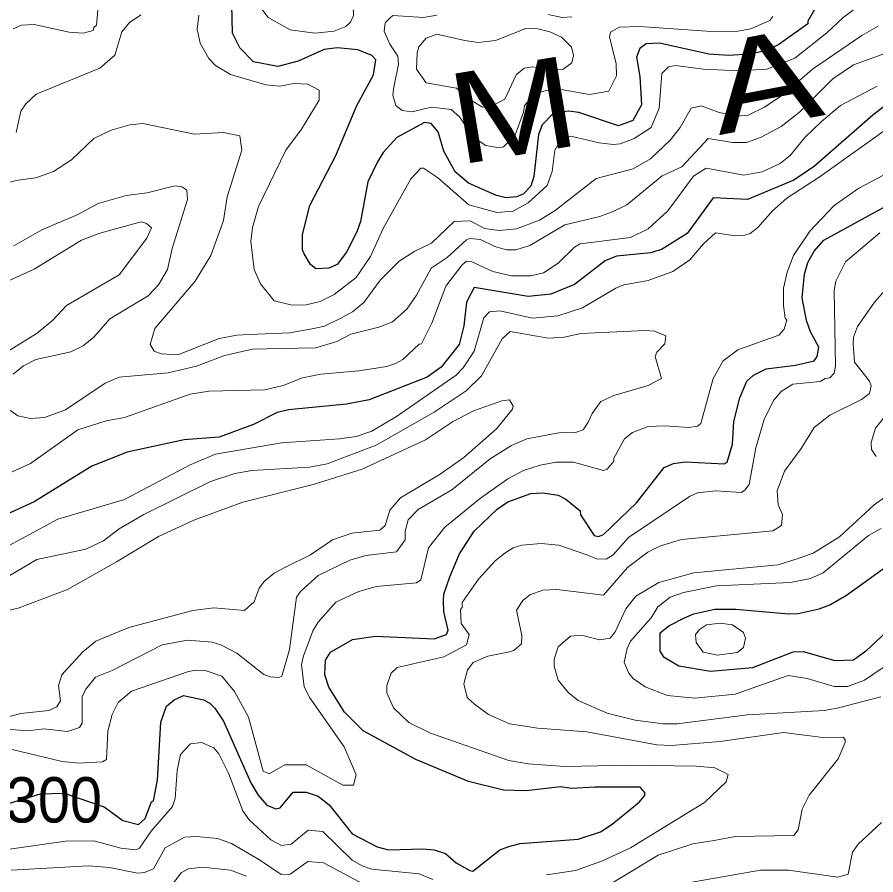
# Model space of a CAD drawing. Extents: x 423 to 448.8, y 7456.3 to 7484.
# Drawn here: x 429.359 to 430.873, y 7468.242 to 7469.755 of the extents above; entities that cross this region are included whole.
import ezdxf
from ezdxf.enums import TextEntityAlignment as Align

# ---------------------------------------------------------------- set-up
doc = ezdxf.new("R2010")
doc.units = 0
doc.header["$LTSCALE"] = 0.032
doc.layers.add('1', color=7, linetype='Continuous', lineweight=25)
doc.layers.add('2', color=7, linetype='Continuous', lineweight=13)
doc.layers.add('61', color=7, linetype='Continuous')

msp = doc.modelspace()

# ---------------------------------------------------------------- linework, layer by layer
at = {"layer": '1'}
for points in [[(430.7694, 7469.7766), (430.7532, 7469.7473), (430.7532, 7469.7426), (430.7022, 7469.7062), (430.679, 7469.6954), (430.6496, 7469.6892), (430.614, 7469.6869), (430.5784, 7469.6892), (430.4918, 7469.7086), (430.4678, 7469.7078), (430.457, 7469.6993), (430.4508, 7469.6838), (430.4569, 7469.6498), (430.46, 7469.6003), (430.4446, 7469.5724), (430.4191, 7469.5632), (430.3495, 7469.5864), (430.3309, 7469.5887), (430.3046, 7469.5856), (430.2845, 7469.5647), (430.2783, 7469.5477), (430.2698, 7469.4735), (430.2644, 7469.4564), (430.2512, 7469.4425), (430.2396, 7469.4379), (430.2211, 7469.4363), (430.2041, 7469.4402), (430.1546, 7469.4618), (430.1313, 7469.4819), (430.1112, 7469.5183), (430.1012, 7469.5523), (430.0888, 7469.567), (430.0772, 7469.5686), (430.0285, 7469.5423), (430.0045, 7469.516), (429.9944, 7469.4998), (429.9774, 7469.4642), (429.9643, 7469.3946), (429.9581, 7469.376), (429.9395, 7469.3404), (429.9233, 7469.3187), (429.9086, 7469.3118), (429.8854, 7469.311), (429.8761, 7469.3188), (429.8653, 7469.3373), (429.8622, 7469.3443), (429.8622, 7469.3714), (429.8753, 7469.4224), (429.921, 7469.5106), (429.9581, 7469.5988), (429.9875, 7469.6529), (429.9913, 7469.6792), (429.9844, 7469.6869), (429.9596, 7469.697), (429.9241, 7469.7008), (429.9001, 7469.6977), (429.8545, 7469.6769), (429.8189, 7469.6676), (429.7755, 7469.6761), (429.7516, 7469.7008), (429.7384, 7469.7263), (429.7376, 7469.7767)], [(430.9064, 7469.6119), (430.8676, 7469.5817), (430.7648, 7469.492), (430.7285, 7469.4673), (430.6465, 7469.4332), (430.5861, 7469.4363), (430.5405, 7469.3729), (430.4964, 7469.3458), (430.4763, 7469.3389), (430.416, 7469.3334), (430.3959, 7469.3249), (430.3417, 7469.2832), (430.3, 7469.2662), (430.2597, 7469.2623), (430.1646, 7469.2777), (430.1515, 7469.2522), (430.1468, 7469.2105), (430.1383, 7469.1772)], [(430.0741, 7468.2885), (430.0942, 7468.2862), (430.1143, 7468.28), (430.1329, 7468.2637), (430.1569, 7468.2498), (430.1622, 7468.249), (430.2102, 7468.2862), (430.2257, 7468.2924), (430.2458, 7468.2978), (430.3479, 7468.3055), (430.3873, 7468.3179), (430.4083, 7468.3318), (430.4554, 7468.3705), (430.4655, 7468.3821), (430.4655, 7468.3875), (430.4577, 7468.3968), (430.3773, 7468.3968), (430.3371, 7468.3944), (430.317, 7468.3975), (430.2567, 7468.3906), (430.2164, 7468.3914), (430.1546, 7468.4068), (430.0617, 7468.4455), (429.9689, 7468.4965), (429.9364, 7468.529), (429.9086, 7468.5731), (429.9016, 7468.5948), (429.9024, 7468.6211), (429.9117, 7468.635), (429.9504, 7468.6574), (429.9906, 7468.6629), (430.0942, 7468.6582), (430.1158, 7468.666), (430.119, 7468.6737), (430.1112, 7468.7062), (430.1105, 7468.7263), (430.1112, 7468.7371), (430.1221, 7468.7681), (430.1391, 7468.8083), (430.1646, 7468.8485), (430.2056, 7468.8872), (430.2242, 7468.9003), (430.2644, 7468.915), (430.286, 7468.9158), (430.3131, 7468.9119), (430.3263, 7468.9049), (430.3518, 7468.884), (430.3525, 7468.8771), (430.3765, 7468.8407), (430.3842, 7468.8392), (430.3928, 7468.8423), (430.4508, 7468.898), (430.4995, 7468.9606), (430.5165, 7468.9676), (430.5366, 7468.9707), (430.6055, 7468.9668), (430.6109, 7468.9699), (430.6202, 7469.0016), (430.6225, 7469.0419), (430.6333, 7469.0836), (430.6457, 7469.113), (430.6573, 7469.1231), (430.6797, 7469.1346), (430.7316, 7469.1409), (430.764, 7469.1486), (430.7694, 7469.1563), (430.7725, 7469.1726), (430.7578, 7469.1997), (430.7509, 7469.2198), (430.7431, 7469.26), (430.747, 7469.3017), (430.7532, 7469.3219), (430.764, 7469.342), (430.781, 7469.3613), (430.9033, 7469.4286)], [(430.1383, 7469.1772), (430.1066, 7469.1377), (430.0819, 7469.12), (429.9798, 7469.0797), (429.9395, 7469.072), (429.8374, 7469.062), (429.8173, 7469.0573), (429.7756, 7469.0364), (429.7152, 7469.014), (429.6534, 7469.0094), (429.5528, 7468.9877), (429.4909, 7468.9629), (429.3888, 7468.9003), (429.327, 7468.8717)], [(430.8924, 7468.6713), (430.8553, 7468.6366), (430.8336, 7468.6211), (430.8012, 7468.6195), (430.7455, 7468.6358), (430.7269, 7468.635), (430.6558, 7468.6072), (430.5815, 7468.601), (430.5258, 7468.6102), (430.4995, 7468.6257), (430.4925, 7468.6365), (430.4925, 7468.669), (430.508, 7468.6814), (430.5359, 7468.6953), (430.5521, 7468.7023), (430.5892, 7468.7108), (430.6264, 7468.7108), (430.7192, 7468.7023), (430.7362, 7468.7031), (430.7733, 7468.7116), (430.7919, 7468.7185), (430.8213, 7468.7356), (430.9218, 7468.8075)], [(429.297, 7468.3543), (429.4002, 7468.3854), (429.4421, 7468.3861), (429.5124, 7468.3625), (429.5456, 7468.3384), (429.5729, 7468.331), (429.5845, 7468.3419), (429.5961, 7468.3712), (429.5992, 7468.3728), (429.6062, 7468.4092), (429.6123, 7468.5113), (429.6193, 7468.5314), (429.6224, 7468.5399), (429.6356, 7468.5507), (429.6525, 7468.5584), (429.6874, 7468.5507), (429.699, 7468.5453), (429.7075, 7468.536), (429.723, 7468.5136), (429.7709, 7468.4045), (429.784, 7468.3829), (429.7995, 7468.3651), (429.815, 7468.3589), (429.8227, 7468.3604), (429.8459, 7468.3883), (429.8684, 7468.3883), (429.89, 7468.3813), (429.9093, 7468.3658), (429.9496, 7468.3148), (429.9937, 7468.2916), (430.0138, 7468.2862), (430.0741, 7468.2885)]]:
    msp.add_lwpolyline(points, dxfattribs=at)
at = {"layer": '2'}
for points in [[(429.9213, 7469.8021), (429.9117, 7469.8122), (429.8637, 7469.8463), (429.8343, 7469.8486), (429.7972, 7469.8385), (429.7817, 7469.8215), (429.7771, 7469.8107), (429.7771, 7469.7999), (429.7833, 7469.7782), (429.8018, 7469.7542), (429.8405, 7469.7325), (429.8838, 7469.7263), (429.9179, 7469.7302), (429.9387, 7469.7379), (429.9465, 7469.7457), (429.9519, 7469.7573), (429.9519, 7469.7666), (429.9426, 7469.7813)], [(430.1484, 7469.7132), (430.1716, 7469.7101), (430.2025, 7469.7132), (430.2559, 7469.7349), (430.2768, 7469.7341), (430.2984, 7469.7287), (430.3185, 7469.7194), (430.3363, 7469.7016), (430.3402, 7469.6869), (430.3371, 7469.6738), (430.3216, 7469.6629), (430.2984, 7469.6622), (430.2675, 7469.6668), (430.2528, 7469.6645), (430.2388, 7469.6529), (430.2187, 7469.6103), (430.1979, 7469.5988), (430.1793, 7469.5957), (430.1569, 7469.6096), (430.1336, 7469.6297), (430.0803, 7469.639), (430.0633, 7469.6629), (430.064, 7469.6916), (430.0671, 7469.7024), (430.0803, 7469.7178), (430.0989, 7469.7248)], [(430.6287, 7468.6342), (430.6395, 7468.6435), (430.6433, 7468.6598), (430.6395, 7468.6698), (430.6202, 7468.683), (430.5985, 7468.6861), (430.5745, 7468.683), (430.5621, 7468.6752), (430.5552, 7468.6659), (430.556, 7468.652), (430.5683, 7468.635), (430.5939, 7468.6296)]]:
    msp.add_lwpolyline(points, close=True, dxfattribs=at)
for points in [[(430.8708, 7469.7952), (430.8151, 7469.7542), (430.7865, 7469.7271), (430.73, 7469.6823), (430.6805, 7469.6629), (430.631, 7469.6598), (430.5691, 7469.6629), (430.5196, 7469.6691), (430.5073, 7469.6668), (430.4956, 7469.6552), (430.491, 7469.5941), (430.4771, 7469.56), (430.4469, 7469.5407), (430.4222, 7469.5314), (430.4098, 7469.5299), (430.385, 7469.533), (430.3355, 7469.5446), (430.3177, 7469.5392), (430.3069, 7469.5199), (430.3023, 7469.4827), (430.2937, 7469.458), (430.2597, 7469.427), (430.2335, 7469.4123), (430.2048, 7469.41), (430.1553, 7469.4239), (430.1004, 7469.4719), (430.0756, 7469.4881), (430.071, 7469.4881), (430.0532, 7469.4696), (430.0045, 7469.3822), (429.982, 7469.3327), (429.9565, 7469.2956), (429.9179, 7469.2654), (429.8931, 7469.253), (429.8684, 7469.2476), (429.8436, 7469.2468), (429.8119, 7469.2545), (429.7879, 7469.2847), (429.7771, 7469.3095), (429.7709, 7469.359), (429.774, 7469.3837), (429.7848, 7469.4209), (429.8328, 7469.5199), (429.8606, 7469.557), (429.8916, 7469.608), (429.8916, 7469.6258), (429.8715, 7469.6366), (429.8467, 7469.6374), (429.822, 7469.6327), (429.7972, 7469.6351), (429.7353, 7469.6536), (429.709, 7469.6691), (429.6967, 7469.6815), (429.6819, 7469.7086), (429.6766, 7469.7333), (429.6796, 7469.7581)], [(429.3664, 7469.7403), (429.3888, 7469.7418), (429.4507, 7469.7279), (429.4755, 7469.7263), (429.4932, 7469.731), (429.494, 7469.7364), (429.4987, 7469.7403), (429.5025, 7469.7797)], [(429.3571, 7469.5515), (429.3656, 7469.5887), (429.3741, 7469.6019), (429.3927, 7469.6189), (429.5049, 7469.6645), (429.5311, 7469.6877), (429.5435, 7469.7287), (429.5574, 7469.7457), (429.5776, 7469.7588)], [(430.6913, 7469.7557), (430.6859, 7469.7488), (430.6527, 7469.7341), (430.6295, 7469.7302), (430.5831, 7469.7295), (430.4562, 7469.738), (430.4206, 7469.7372), (430.4052, 7469.7279), (430.4036, 7469.7194), (430.4152, 7469.673), (430.416, 7469.6514), (430.402, 7469.6243), (430.368, 7469.6181), (430.3216, 7469.6266), (430.3, 7469.6273), (430.2729, 7469.6204), (430.2536, 7469.5988), (430.252, 7469.5871), (430.2365, 7469.5454), (430.2164, 7469.526), (430.2087, 7469.5245), (430.1855, 7469.5283), (430.1584, 7469.5461), (430.1576, 7469.5515), (430.139, 7469.5786), (430.1244, 7469.5918), (430.0896, 7469.5957), (430.0556, 7469.5879), (430.0377, 7469.5902), (430.0269, 7469.5987), (430.0215, 7469.6173), (430.0223, 7469.6281), (430.0315, 7469.6715), (430.03, 7469.6861), (430.0161, 7469.707), (430.006, 7469.7302), (430.0076, 7469.7449), (430.0161, 7469.7526), (430.0215, 7469.7573), (430.0757, 7469.7542), (430.0989, 7469.758)], [(430.2953, 7469.7596), (430.3201, 7469.7542), (430.3371, 7469.755)], [(429.3517, 7469.7341), (429.3664, 7469.7403)], [(430.877, 7469.7387), (430.8483, 7469.7225), (430.761, 7469.6629), (430.7106, 7469.6188), (430.6766, 7469.5957), (430.648, 7469.5817), (430.6279, 7469.5802), (430.597, 7469.5863), (430.5652, 7469.598), (430.5474, 7469.5941), (430.5281, 7469.5601), (430.5111, 7469.5384), (430.4755, 7469.5051), (430.4454, 7469.4873), (430.3796, 7469.4704), (430.3077, 7469.4139), (430.2798, 7469.3969), (430.2396, 7469.3814), (430.2087, 7469.3783), (430.1832, 7469.3821), (430.1577, 7469.3953), (430.1298, 7469.3946), (430.0895, 7469.3559), (430.0602, 7469.342), (430.0324, 7469.3242), (429.9999, 7469.2917), (429.9705, 7469.2515), (429.9503, 7469.2352), (429.931, 7469.2244), (429.9009, 7469.2097), (429.8792, 7469.205), (429.839, 7469.1981), (429.7678, 7469.195), (429.7462, 7469.1942), (429.7152, 7469.188), (429.6425, 7469.1594), (429.6131, 7469.1609), (429.6007, 7469.1656), (429.5938, 7469.1772), (429.6015, 7469.2058), (429.6727, 7469.2894), (429.7005, 7469.3342), (429.723, 7469.3961), (429.7291, 7469.4379), (429.7554, 7469.5199), (429.7516, 7469.5454), (429.723, 7469.5515), (429.6719, 7469.5484), (429.5806, 7469.567), (429.5574, 7469.5647)], [(430.8955, 7469.6931), (430.8337, 7469.6707), (430.7973, 7469.6459), (430.7385, 7469.5871), (430.706, 7469.5616), (430.6697, 7469.5423), (430.6449, 7469.5337), (430.6202, 7469.5337), (430.5776, 7469.5407), (430.5312, 7469.4905), (430.4964, 7469.475), (430.4338, 7469.4239), (430.4113, 7469.4123), (430.3866, 7469.403), (430.3247, 7469.3883), (430.2628, 7469.352), (430.2381, 7469.3443), (430.2218, 7469.3443), (430.201, 7469.3504), (430.1762, 7469.3628), (430.1569, 7469.3644), (430.1515, 7469.3621), (430.1174, 7469.3311), (430.0888, 7469.3118), (430.0632, 7469.2646), (430.0462, 7469.2399), (430.0207, 7469.2174), (429.9968, 7469.2081), (429.9473, 7469.1958), (429.9225, 7469.1826), (429.8854, 7469.1718), (429.8235, 7469.1703), (429.774, 7469.1695), (429.7245, 7469.1579), (429.675, 7469.1393), (429.6255, 7469.1277), (429.5389, 7469.12), (429.5141, 7469.1091), (429.4445, 7469.062), (429.4074, 7469.0488), (429.3826, 7469.0472), (429.3602, 7469.0519), (429.3416, 7469.065)], [(430.8754, 7469.6327), (430.8105, 7469.5987), (430.7772, 7469.5709), (430.7478, 7469.5423), (430.7222, 7469.5106), (430.7045, 7469.4967), (430.6728, 7469.4819), (430.6403, 7469.4758), (430.5738, 7469.4881), (430.5513, 7469.4742), (430.5065, 7469.4131), (430.4716, 7469.3814), (430.4407, 7469.3659), (430.3518, 7469.3551), (430.3417, 7469.3489), (430.3131, 7469.3211), (430.2868, 7469.304), (430.2644, 7469.2986), (430.2304, 7469.2986), (430.1979, 7469.3064), (430.1607, 7469.3234), (430.1515, 7469.3242), (430.1437, 7469.318), (430.1151, 7469.2801), (430.0903, 7469.2151), (430.0718, 7469.1787), (430.0679, 7469.178), (430.0393, 7469.1509), (430.0262, 7469.1439), (430.0107, 7469.1385), (429.9612, 7469.1308), (429.8947, 7469.1254), (429.8622, 7469.1184), (429.8282, 7469.1053), (429.7957, 7469.0975), (429.6967, 7469.0952), (429.6642, 7469.0898), (429.5482, 7469.0488), (429.5157, 7469.0426), (429.4662, 7469.0271), (429.3826, 7468.9676), (429.3502, 7468.9529)], [(430.9001, 7469.5631), (430.7748, 7469.4735), (430.7161, 7469.4355), (430.6905, 7469.4131), (430.665, 7469.3837), (430.6511, 7469.3729), (430.6403, 7469.3698), (430.6248, 7469.369), (430.59, 7469.3744), (430.5691, 7469.3551), (430.5451, 7469.3265), (430.515, 7469.3064), (430.4717, 7469.2901), (430.4284, 7469.2824), (430.4144, 7469.277), (430.3557, 7469.2422), (430.3123, 7469.2282), (430.2675, 7469.2236), (430.2102, 7469.2368), (430.1917, 7469.2352), (430.1816, 7469.2244), (430.1646, 7469.1656), (430.1452, 7469.1362), (430.1329, 7469.1231), (430.0277, 7469.0503), (429.9844, 7469.0248), (429.9566, 7469.0155), (429.9272, 7469.0109), (429.8251, 7469.0039), (429.709, 7468.9838), (429.6642, 7468.9653), (429.5482, 7468.9042), (429.4306, 7468.8694), (429.344, 7468.8222)], [(429.5574, 7469.5647), (429.525, 7469.5554), (429.494, 7469.5407), (429.4546, 7469.5028), (429.4229, 7469.4827), (429.3919, 7469.4711), (429.361, 7469.4672), (429.3455, 7469.4634)], [(429.3502, 7468.4633), (429.4383, 7468.4424), (429.4677, 7468.4393), (429.5095, 7468.4416), (429.5164, 7468.4455), (429.5187, 7468.4958), (429.5265, 7468.5252), (429.5373, 7468.5461), (429.5605, 7468.5662), (429.6611, 7468.601), (429.675, 7468.6033), (429.6905, 7468.6025), (429.7199, 7468.5925), (429.7423, 7468.5654), (429.767, 7468.5206), (429.7925, 7468.4254), (429.8034, 7468.4207), (429.8312, 7468.4362), (429.8683, 7468.4362), (429.9333, 7468.4007), (429.9519, 7468.4006), (429.9565, 7468.4184), (429.9356, 7468.468), (429.8753, 7468.5546), (429.8652, 7468.5739), (429.8606, 7468.6134), (429.8637, 7468.6288), (429.8807, 7468.6737), (429.89, 7468.6876), (429.9209, 7468.7232), (429.9612, 7468.7418), (429.9921, 7468.751), (430.0633, 7468.7572), (430.071, 7468.7626), (430.0842, 7468.8191), (430.1128, 7468.8554), (430.1762, 7468.9065), (430.2242, 7468.9405), (430.252, 7468.9552), (430.2814, 7468.9645), (430.3092, 7468.9699), (430.3402, 7468.9699), (430.3928, 7468.9552), (430.399, 7468.9575), (430.4113, 7468.9715), (430.4113, 7468.9768), (430.4299, 7469.0109), (430.4438, 7469.0225), (430.4717, 7469.0326), (430.5011, 7469.0341), (430.5428, 7469.031), (430.5583, 7469.0333), (430.5645, 7469.038), (430.5861, 7469.1177), (430.6039, 7469.1486), (430.6295, 7469.1679), (430.7022, 7469.1942), (430.7114, 7469.2043), (430.7161, 7469.2205), (430.713, 7469.2236), (430.7099, 7469.2461), (430.7099, 7469.277), (430.7168, 7469.3048), (430.7277, 7469.3342), (430.7563, 7469.3775), (430.7996, 7469.4224), (430.8429, 7469.4533), (430.9489, 7469.509)], [(429.3517, 7469.1254), (429.3703, 7469.1401), (429.3919, 7469.1509), (429.4538, 7469.1648), (429.4755, 7469.1749), (429.494, 7469.1903), (429.5226, 7469.2228), (429.5899, 7469.2631), (429.6085, 7469.2824), (429.624, 7469.3095), (429.6324, 7469.3466), (429.6595, 7469.4332), (429.658, 7469.4494), (429.6495, 7469.4556), (429.6379, 7469.4572), (429.6255, 7469.4541), (429.5884, 7469.4448), (429.5513, 7469.4402), (429.5018, 7469.4263), (429.4646, 7469.4061), (429.4028, 7469.3798), (429.3533, 7469.3512)], [(429.3354, 7469.161), (429.3942, 7469.1973), (429.4221, 7469.2205), (429.446, 7469.2461), (429.5389, 7469.3002), (429.5876, 7469.3652), (429.5961, 7469.3829), (429.5868, 7469.3907), (429.5783, 7469.3938), (429.5714, 7469.3922), (429.5049, 7469.3737), (429.4724, 7469.3613), (429.3888, 7469.3102), (429.3239, 7469.2808)], [(430.0107, 7468.5631), (430.0107, 7468.5762), (430.0184, 7468.5979), (430.0293, 7468.6079), (430.1112, 7468.6265), (430.1515, 7468.6481), (430.1561, 7468.6659), (430.1421, 7468.6853), (430.1406, 7468.71), (430.1437, 7468.7139), (430.1437, 7468.7224), (430.1723, 7468.7634), (430.2017, 7468.7959), (430.2187, 7468.8098), (430.2335, 7468.8191), (430.2489, 7468.8237), (430.283, 7468.8268), (430.3139, 7468.8237), (430.3634, 7468.8067), (430.3804, 7468.7997), (430.3974, 7468.799), (430.4098, 7468.8067), (430.4368, 7468.8369), (430.5444, 7468.9096), (430.5583, 7468.9158), (430.5908, 7468.9196), (430.6356, 7468.9165), (430.6418, 7468.9204), (430.6496, 7468.9305), (430.6611, 7468.9955), (430.6758, 7469.045), (430.6928, 7469.079), (430.706, 7469.0945), (430.7269, 7469.1076), (430.7749, 7469.1122), (430.7834, 7469.1176), (430.7918, 7469.1184), (430.7996, 7469.1269), (430.8019, 7469.1393), (430.7996, 7469.2724), (430.8027, 7469.2894), (430.8197, 7469.3234), (430.8801, 7469.3744)], [(430.3773, 7468.2096), (430.4894, 7468.2769), (430.5506, 7468.297), (430.5877, 7468.3032), (430.6248, 7468.3102), (430.7284, 7468.3117), (430.7362, 7468.3217), (430.7431, 7468.3581), (430.7555, 7468.3829), (430.8066, 7468.447), (430.8189, 7468.4757), (430.8189, 7468.4811), (430.8151, 7468.485), (430.7842, 7468.4842), (430.7099, 7468.4935), (430.5985, 7468.4772), (430.5119, 7468.4702), (430.4871, 7468.4718), (430.3634, 7468.4943), (430.2768, 7468.5012), (430.2273, 7468.5089), (430.1901, 7468.5252), (430.1654, 7468.543), (430.1522, 7468.5553), (430.1468, 7468.5793), (430.153, 7468.6041), (430.1631, 7468.6165), (430.1886, 7468.628), (430.2272, 7468.6358), (430.235, 7468.6381), (430.2481, 7468.6497), (430.2489, 7468.6644), (430.2396, 7468.7093), (430.2505, 7468.7263), (430.2628, 7468.7363), (430.286, 7468.7441), (430.3108, 7468.7456), (430.3927, 7468.7356), (430.4353, 7468.7843), (430.4709, 7468.8114), (430.4933, 7468.8222), (430.5305, 7468.8338), (430.6913, 7468.8492), (430.7068, 7468.8585), (430.7083, 7468.8778), (430.7006, 7468.8949), (430.6991, 7468.9197), (430.7122, 7468.9544), (430.7416, 7468.9939), (430.764, 7469.031), (430.7919, 7469.0527), (430.8476, 7469.0805), (430.8615, 7469.0913), (430.8646, 7469.1045), (430.8615, 7469.113), (430.8352, 7469.1463), (430.8328, 7469.178), (430.8336, 7469.1904), (430.8406, 7469.2089), (430.8707, 7469.2522), (430.962, 7469.3558)], [(429.3331, 7468.4996), (429.378, 7468.4965), (429.4058, 7468.4996), (429.4476, 7468.495), (429.4692, 7468.502), (429.4739, 7468.5097), (429.4739, 7468.5561), (429.4801, 7468.57), (429.4971, 7468.5909), (429.5265, 7468.6025), (429.6147, 7468.6481), (429.6595, 7468.6559), (429.7029, 7468.6528), (429.7183, 7468.6481), (429.7462, 7468.6334), (429.7941, 7468.5956), (429.805, 7468.5917), (429.8204, 7468.5902), (429.8258, 7468.5925), (429.839, 7468.6397), (429.8513, 7468.7317), (429.8583, 7468.7418), (429.89, 7468.7703), (429.9457, 7468.7974), (429.9736, 7468.8052), (430.0277, 7468.8121), (430.0432, 7468.833), (430.0432, 7468.8485), (430.0486, 7468.8686), (430.0663, 7468.8864), (430.1252, 7468.9212), (430.1932, 7468.9761), (430.2304, 7468.9993), (430.2574, 7469.0109), (430.3139, 7469.0218), (430.3433, 7469.0225), (430.3572, 7469.0272), (430.3657, 7469.0403), (430.3726, 7469.0558), (430.3881, 7469.0767), (430.4113, 7469.0875), (430.4717, 7469.1052), (430.4949, 7469.1176), (430.484, 7469.1563), (430.4871, 7469.164), (430.5011, 7469.1787), (430.5026, 7469.1927), (430.4825, 7469.2012), (430.467, 7469.2019), (430.3526, 7469.1966)], [(430.3526, 7469.1966), (430.3232, 7469.1904), (430.2953, 7469.1888), (430.228, 7469.2004), (430.2141, 7469.1872), (430.1778, 7469.1223), (430.1507, 7469.096), (430.0942, 7469.0581), (429.9921, 7469.0001), (429.9055, 7468.9668), (429.8746, 7468.9614), (429.7725, 7468.9552), (429.7431, 7468.9498), (429.6998, 7468.9359), (429.5822, 7468.8779), (429.5389, 7468.8524), (429.511, 7468.8315), (429.4801, 7468.8168), (429.3935, 7468.7982), (429.3347, 7468.7634)], [(429.3409, 7468.5205), (429.3656, 7468.5267), (429.4151, 7468.5321), (429.429, 7468.5383), (429.4352, 7468.5492), (429.4321, 7468.5762), (429.4375, 7468.5948), (429.4747, 7468.6358), (429.4979, 7468.6543), (429.5559, 7468.6783), (429.6688, 7468.7085), (429.706, 7468.7131), (429.7601, 7468.7085), (429.7771, 7468.7239), (429.7856, 7468.748), (429.7949, 7468.7603), (429.8119, 7468.7742), (429.8312, 7468.7843), (429.8761, 7468.8067), (429.9148, 7468.833), (429.9488, 7468.8446), (429.9983, 7468.85), (430.0076, 7468.8585), (430.0161, 7468.8856), (430.0347, 7468.9073), (430.105, 7468.949), (430.1468, 7468.9784), (430.2041, 7469.0287), (430.2326, 7469.0635), (430.2334, 7469.0689), (430.2273, 7469.0798), (430.2133, 7469.0782), (430.1638, 7469.0604), (430.1267, 7469.0411), (430.0788, 7469.0093), (429.9674, 7468.9575), (429.8808, 7468.9305), (429.757, 7468.8995), (429.6704, 7468.8678), (429.6085, 7468.8392), (429.5342, 7468.7943), (429.4476, 7468.7456), (429.361, 7468.7124), (429.3239, 7468.7046)], [(430.8886, 7469.0504), (430.8723, 7469.0302), (430.8646, 7469.0047), (430.8653, 7468.9924), (430.8738, 7468.98)], [(430.904, 7468.9189), (430.87, 7468.8949), (430.8089, 7468.8384), (430.7625, 7468.8098), (430.7377, 7468.8005), (430.7006, 7468.7889), (430.5521, 7468.775), (430.4902, 7468.758), (430.45, 7468.734), (430.4322, 7468.7116), (430.4136, 7468.6706), (430.4044, 7468.6597), (430.3858, 7468.6566), (430.3541, 7468.6652), (430.3347, 7468.6629), (430.3131, 7468.6443), (430.3061, 7468.6227), (430.3061, 7468.6103), (430.3131, 7468.5855), (430.3309, 7468.5631), (430.3479, 7468.5499), (430.399, 7468.5275), (430.4485, 7468.5151), (430.498, 7468.5089), (430.5227, 7468.5089), (430.6465, 7468.5244), (430.7826, 7468.5321), (430.8074, 7468.5368), (430.8816, 7468.5561)], [(430.8824, 7468.8531), (430.86, 7468.8407), (430.7803, 7468.775), (430.7579, 7468.7649), (430.7223, 7468.758), (430.5923, 7468.7518)], [(430.5923, 7468.7518), (430.5336, 7468.7402), (430.5103, 7468.7317), (430.4886, 7468.7147), (430.4771, 7468.6953), (430.4407, 7468.6543), (430.4345, 7468.6412), (430.4291, 7468.6165), (430.4376, 7468.5979), (430.4454, 7468.5886), (430.4662, 7468.5739), (430.5057, 7468.5584), (430.5537, 7468.5538), (430.6248, 7468.5608), (430.7184, 7468.594), (430.7517, 7468.5886), (430.7996, 7468.5747), (430.8228, 7468.5747), (430.853, 7468.5855), (430.9334, 7468.6404)], [(430.2922, 7468.2421), (430.3433, 7468.2498), (430.3912, 7468.2668), (430.4407, 7468.29), (430.5707, 7468.3697), (430.6093, 7468.4061), (430.6124, 7468.4192), (430.5892, 7468.4308), (430.5568, 7468.4339), (430.4407, 7468.4355), (430.3247, 7468.4331), (430.2597, 7468.4378), (430.2257, 7468.4439), (430.088, 7468.4919), (430.0494, 7468.5112), (430.0223, 7468.5368), (430.0107, 7468.5631)], [(429.3285, 7468.2854), (429.4445, 7468.3016), (429.494, 7468.3024), (429.542, 7468.2893), (429.5682, 7468.2862), (429.5745, 7468.2893), (429.5953, 7468.3195), (429.6332, 7468.3628), (429.6379, 7468.3767), (429.641, 7468.4262), (429.6471, 7468.4548), (429.6649, 7468.4734), (429.6843, 7468.4757), (429.706, 7468.4664), (429.7144, 7468.4556), (429.7314, 7468.4216), (429.757, 7468.355), (429.7678, 7468.3396), (429.8065, 7468.3039), (429.8251, 7468.2939), (429.8421, 7468.2962), (429.8722, 7468.321), (429.8977, 7468.3187), (429.9496, 7468.2684), (429.9674, 7468.2583), (429.9844, 7468.2521), (430.0679, 7468.2444), (430.0919, 7468.2343)], [(430.8832, 7468.3349), (430.8421, 7468.2962), (430.8321, 7468.2823), (430.8244, 7468.2436), (430.8058, 7468.2382), (430.7192, 7468.2506), (430.6697, 7468.2506), (430.4717, 7468.2158)], [(429.3486, 7468.2506), (429.4847, 7468.2583), (429.5219, 7468.2552), (429.5714, 7468.2452), (429.5837, 7468.2467), (429.5992, 7468.2529), (429.6201, 7468.2901), (429.6541, 7468.3086), (429.675, 7468.3101), (429.7121, 7468.3063), (429.7369, 7468.2978), (429.7864, 7468.2691), (429.8243, 7468.2428), (429.8405, 7468.2436), (429.8714, 7468.2661), (429.8993, 7468.2638), (429.9798, 7468.2204)], [(429.7631, 7468.2398), (429.7353, 7468.2506), (429.6858, 7468.256), (429.6611, 7468.2529), (429.6487, 7468.2467), (429.6348, 7468.2281)]]:
    msp.add_lwpolyline(points, dxfattribs=at)

# ---------------------------------------------------------------- texts
at = {"layer": '61'}
for s, rotation, width, p in [('A', 10.78, 1.35, (430.6908, 7469.5645)), ('M', 9.439, 1.25, (430.2463, 7469.5121))]:
    msp.add_text(s, height=0.16, rotation=rotation, dxfattribs=dict(at, width=width)).set_placement(p, align=Align.CENTER)
at = {"layer": '61', "width": 0.95}
msp.add_text('1300', height=0.08, dxfattribs=at).set_placement((429.3956, 7468.3346), align=Align.CENTER)

doc.saveas('drawing.dxf')
